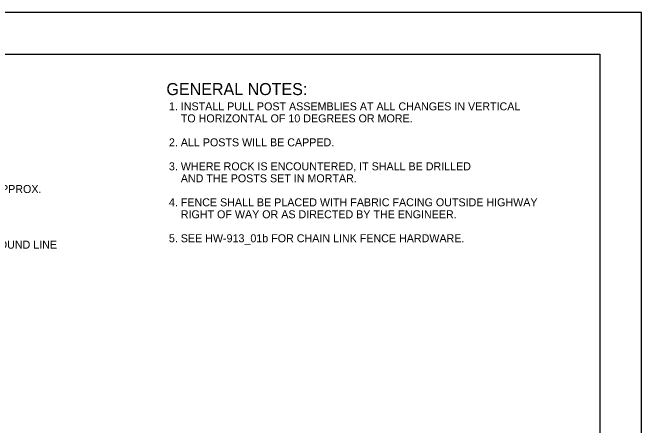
# Model space of a CAD drawing. Extents: x 0 to 2.85, y -0.1 to 1.83.
# Drawn here: x 2.047 to 2.833, y 1.317 to 1.833 of the extents above; entities that cross this region are included whole.
import ezdxf

# ---------------------------------------------------------------- set-up
doc = ezdxf.new("R2010")
doc.units = 0
for name, color, linetype in [('BDR_Inner_Perimeter', 7, 'Continuous'), ('BDR_Outer_Perimeter', 7, 'Continuous'), ('CT_CSHT_GeneralLabel', 7, 'Continuous'), ('CT_Dimensions', 7, 'Continuous')]:
    doc.layers.add(name, color=color, linetype=linetype)

msp = doc.modelspace()

# ---------------------------------------------------------------- linework, layer by layer
at = {"layer": 'BDR_Inner_Perimeter'}
msp.add_lwpolyline([(0.13539, 1.78125), (2.78123, 1.78125), (2.78123, 0.05208), (0.13539, 0.05208)], close=True, dxfattribs=at)
at = {"layer": 'BDR_Outer_Perimeter'}
msp.add_lwpolyline([(0, 0), (2.83333, 0), (2.83333, 1.83333), (0, 1.83333)], close=True, dxfattribs=at)

# ---------------------------------------------------------------- texts
at = {"layer": 'CT_CSHT_GeneralLabel'}
msp.add_text('GENERAL NOTES:', height=0.015, dxfattribs=at).set_placement((2.23974, 1.73011))
at = {"layer": 'CT_Dimensions'}
for s, p in [('1. INSTALL PULL POST ASSEMBLIES AT ALL CHANGES IN VERTICAL', (2.24284, 1.71099)), ('    TO HORIZONTAL OF 10 DEGREES OR MORE.', (2.24284, 1.69599)), ('2. ALL POSTS WILL BE CAPPED.', (2.24284, 1.66599)), ('3. WHERE ROCK IS ENCOUNTERED, IT SHALL BE DRILLED ', (2.24284, 1.63599)), ('    AND THE POSTS SET IN MORTAR.', (2.24284, 1.62099)), ("2'' APPROX.", (2.00787, 1.60762)), ('4. FENCE SHALL BE PLACED WITH FABRIC FACING OUTSIDE HIGHWAY ', (2.24284, 1.59099)), ('    RIGHT OF WAY OR AS DIRECTED BY THE ENGINEER.', (2.24284, 1.57599)), ('5. SEE HW-913_01b FOR CHAIN LINK FENCE HARDWARE.', (2.24284, 1.54599)), ('GROUND LINE', (2.01019, 1.53802))]:
    msp.add_text(s, height=0.01, dxfattribs=at).set_placement(p)

doc.saveas('drawing.dxf')
